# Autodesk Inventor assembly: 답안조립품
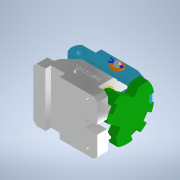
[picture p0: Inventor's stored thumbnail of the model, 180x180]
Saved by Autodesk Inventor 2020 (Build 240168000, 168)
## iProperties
Created: 2022-08
Part Number: 답안조립품
Document SubType Name: Assembly
Designer: com
Author: com
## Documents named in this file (8)
- C:\Users\com\Desktop\720806V1011\답안조립품.iam
- C:\Users\com\Desktop\720806V1011\1. 본체.ipt
- C:\Users\com\Desktop\720806V1011\부시.ipt
- C:\Users\com\Desktop\720806V1011\분할축.ipt
- C:\Users\com\Desktop\720806V1011\분할대.ipt
- C:\Users\com\Desktop\720806V1011\와셔.ipt
- C:\Users\com\Desktop\720806V1011\클레비스핀.ipt
- C:\Users\com\Desktop\720806V1011\분할핀.ipt
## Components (1 placed, 1 different names)
1. 1. 본체:1
